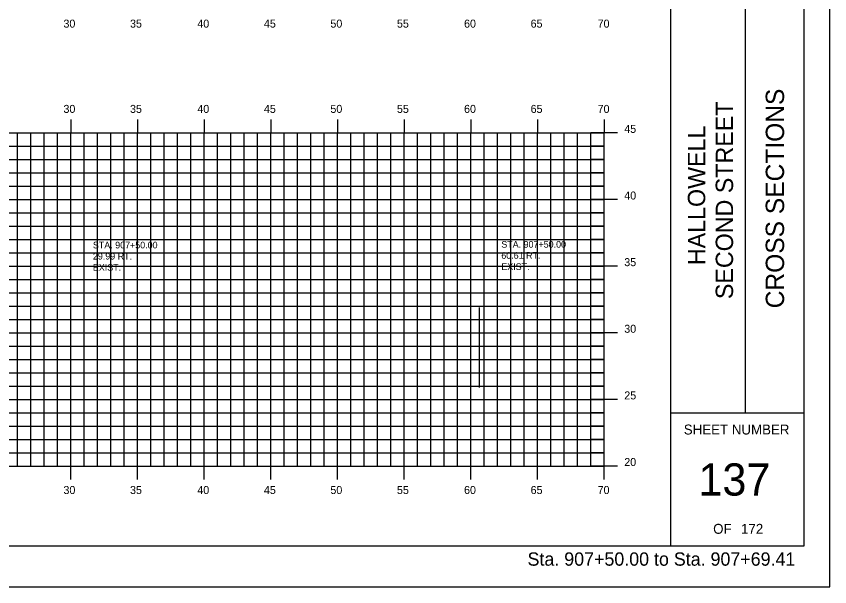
# Model space of a CAD drawing. Extents: x 1025909 to 1026079, y 394697 to 394807.
# Drawn here: x 1026017.6 to 1026078.6, y 394696.5 to 394739.4 of the extents above; entities that cross this region are included whole.
import ezdxf

# ---------------------------------------------------------------- set-up
doc = ezdxf.new("R2010")
doc.units = 0
for name, color, linetype in [('BORDER', 7, 'Continuous'), ('D_Text_Monospaced', 7, 'Continuous'), ('H_V ANNOTATION', 7, 'Continuous'), ('HIGHWAY_TITLE', 7, 'Continuous'), ('MAJOR', 7, 'Continuous'), ('MINOR', 7, 'Continuous'), ('PLOT BOUNDARY', 7, 'Continuous'), ('S_Utilities_UG_Sanitary_Sewer', 7, 'Continuous')]:
    doc.layers.add(name, color=color, linetype=linetype)

msp = doc.modelspace()

# ---------------------------------------------------------------- linework, layer by layer
at = {"layer": 'BORDER'}
for p, q in [((1026066.677, 394699.607), (1026066.677, 394804.61)), ((1026076.677, 394699.607), (1026076.677, 394804.607)), ((1026072.268, 394709.61), (1026072.268, 394744.61)), ((1026066.677, 394709.61), (1026076.677, 394709.61)), ((1025916.677, 394699.607), (1026076.677, 394699.607))]:
    msp.add_line(p, q, dxfattribs=at)
at = {"layer": 'MAJOR'}
for p, q in [((1026021.677, 394731.609), (1026021.677, 394730.607)), ((1026026.677, 394731.609), (1026026.677, 394730.607)), ((1026031.677, 394731.609), (1026031.677, 394730.607)), ((1026036.677, 394731.609), (1026036.677, 394730.607)), ((1026041.677, 394731.609), (1026041.677, 394730.607)), ((1026046.677, 394731.609), (1026046.677, 394730.607)), ((1026051.677, 394731.609), (1026051.677, 394730.607)), ((1026056.677, 394731.609), (1026056.677, 394730.607)), ((1026061.677, 394731.609), (1026061.677, 394730.607)), ((1025921.677, 394730.607), (1026061.677, 394730.607)), ((1026021.677, 394705.607), (1026021.677, 394730.607)), ((1026026.677, 394705.607), (1026026.677, 394730.607)), ((1026031.677, 394705.607), (1026031.677, 394730.607)), ((1026036.677, 394705.607), (1026036.677, 394730.607)), ((1026041.677, 394705.607), (1026041.677, 394730.607)), ((1026046.677, 394705.607), (1026046.677, 394730.607)), ((1026051.677, 394705.607), (1026051.677, 394730.607)), ((1026056.677, 394705.607), (1026056.677, 394730.607)), ((1026062.679, 394730.607), (1026060.675, 394730.607)), ((1026061.677, 394705.607), (1026061.677, 394730.607)), ((1025921.677, 394725.607), (1026061.677, 394725.607)), ((1026062.679, 394725.607), (1026060.675, 394725.607)), ((1025921.677, 394720.607), (1026061.677, 394720.607)), ((1026062.679, 394720.607), (1026060.675, 394720.607)), ((1025921.677, 394715.607), (1026061.677, 394715.607)), ((1026062.679, 394715.607), (1026060.675, 394715.607)), ((1025921.677, 394710.607), (1026061.677, 394710.607)), ((1026062.679, 394710.607), (1026060.675, 394710.607)), ((1025921.677, 394705.607), (1026061.677, 394705.607)), ((1026021.677, 394704.605), (1026021.677, 394705.607)), ((1026026.677, 394704.605), (1026026.677, 394705.607)), ((1026031.677, 394704.605), (1026031.677, 394705.607)), ((1026036.677, 394704.605), (1026036.677, 394705.607)), ((1026041.677, 394704.605), (1026041.677, 394705.607)), ((1026046.677, 394704.605), (1026046.677, 394705.607)), ((1026051.677, 394704.605), (1026051.677, 394705.607)), ((1026056.677, 394704.605), (1026056.677, 394705.607)), ((1026062.679, 394705.607), (1026060.675, 394705.607)), ((1026061.677, 394704.605), (1026061.677, 394705.607))]:
    msp.add_line(p, q, dxfattribs=at)
at = {"layer": 'MINOR'}
for p, q in [((1026017.677, 394705.607), (1026017.677, 394730.607)), ((1026018.677, 394705.607), (1026018.677, 394730.607)), ((1026019.677, 394705.607), (1026019.677, 394730.607)), ((1026020.677, 394705.607), (1026020.677, 394730.607)), ((1026022.677, 394705.607), (1026022.677, 394730.607)), ((1026023.677, 394705.607), (1026023.677, 394730.607)), ((1026024.677, 394705.607), (1026024.677, 394730.607)), ((1026025.677, 394705.607), (1026025.677, 394730.607)), ((1026027.677, 394705.607), (1026027.677, 394730.607)), ((1026028.677, 394705.607), (1026028.677, 394730.607)), ((1026029.677, 394705.607), (1026029.677, 394730.607)), ((1026030.677, 394705.607), (1026030.677, 394730.607)), ((1026032.677, 394705.607), (1026032.677, 394730.607)), ((1026033.677, 394705.607), (1026033.677, 394730.607)), ((1026034.677, 394705.607), (1026034.677, 394730.607)), ((1026035.677, 394705.607), (1026035.677, 394730.607)), ((1026037.677, 394705.607), (1026037.677, 394730.607)), ((1026038.677, 394705.607), (1026038.677, 394730.607)), ((1026039.677, 394705.607), (1026039.677, 394730.607)), ((1026040.677, 394705.607), (1026040.677, 394730.607)), ((1026042.677, 394705.607), (1026042.677, 394730.607)), ((1026043.677, 394705.607), (1026043.677, 394730.607)), ((1026044.677, 394705.607), (1026044.677, 394730.607)), ((1026045.677, 394705.607), (1026045.677, 394730.607)), ((1026047.677, 394705.607), (1026047.677, 394730.607)), ((1026048.677, 394705.607), (1026048.677, 394730.607)), ((1026049.677, 394705.607), (1026049.677, 394730.607)), ((1026050.677, 394705.607), (1026050.677, 394730.607)), ((1026052.677, 394705.607), (1026052.677, 394730.607)), ((1026053.677, 394705.607), (1026053.677, 394730.607)), ((1026054.677, 394705.607), (1026054.677, 394730.607)), ((1026055.677, 394705.607), (1026055.677, 394730.607)), ((1026057.677, 394705.607), (1026057.677, 394730.607)), ((1026058.677, 394705.607), (1026058.677, 394730.607)), ((1026059.677, 394705.607), (1026059.677, 394730.607)), ((1026060.677, 394705.607), (1026060.677, 394730.607)), ((1025921.677, 394729.607), (1026061.677, 394729.607)), ((1026061.677, 394729.607), (1026060.675, 394729.607)), ((1025921.677, 394728.607), (1026061.677, 394728.607)), ((1026061.677, 394728.607), (1026060.675, 394728.607)), ((1025921.677, 394727.607), (1026061.677, 394727.607)), ((1026061.677, 394727.607), (1026060.675, 394727.607)), ((1025921.677, 394726.607), (1026061.677, 394726.607)), ((1026061.677, 394726.607), (1026060.675, 394726.607)), ((1025921.677, 394724.607), (1026061.677, 394724.607)), ((1026061.677, 394724.607), (1026060.675, 394724.607)), ((1025921.677, 394723.607), (1026061.677, 394723.607)), ((1026061.677, 394723.607), (1026060.675, 394723.607)), ((1025921.677, 394722.607), (1026061.677, 394722.607)), ((1026061.677, 394722.607), (1026060.675, 394722.607)), ((1025921.677, 394721.607), (1026061.677, 394721.607)), ((1026061.677, 394721.607), (1026060.675, 394721.607)), ((1025921.677, 394719.607), (1026061.677, 394719.607)), ((1026061.677, 394719.607), (1026060.675, 394719.607)), ((1025921.677, 394718.607), (1026061.677, 394718.607)), ((1026061.677, 394718.607), (1026060.675, 394718.607)), ((1025921.677, 394717.607), (1026061.677, 394717.607)), ((1026061.677, 394717.607), (1026060.675, 394717.607)), ((1025921.677, 394716.607), (1026061.677, 394716.607)), ((1026061.677, 394716.607), (1026060.675, 394716.607)), ((1025921.677, 394714.607), (1026061.677, 394714.607)), ((1026061.677, 394714.607), (1026060.675, 394714.607)), ((1025921.677, 394713.607), (1026061.677, 394713.607)), ((1026061.677, 394713.607), (1026060.675, 394713.607)), ((1025921.677, 394712.607), (1026061.677, 394712.607)), ((1026061.677, 394712.607), (1026060.675, 394712.607)), ((1025921.677, 394711.607), (1026061.677, 394711.607)), ((1026061.677, 394711.607), (1026060.675, 394711.607)), ((1025921.677, 394709.607), (1026061.677, 394709.607)), ((1026061.677, 394709.607), (1026060.675, 394709.607)), ((1025921.677, 394708.607), (1026061.677, 394708.607)), ((1026061.677, 394708.607), (1026060.675, 394708.607)), ((1025921.677, 394707.607), (1026061.677, 394707.607)), ((1026061.677, 394707.607), (1026060.675, 394707.607)), ((1025921.677, 394706.607), (1026061.677, 394706.607)), ((1026061.677, 394706.607), (1026060.675, 394706.607))]:
    msp.add_line(p, q, dxfattribs=at)
at = {"layer": 'PLOT BOUNDARY'}
msp.add_lwpolyline([(1025908.583, 394696.548), (1026078.583, 394696.548), (1026078.583, 394806.548), (1025908.583, 394806.548)], close=True, dxfattribs=at)
at = {"layer": 'S_Utilities_UG_Sanitary_Sewer'}
for p, q in [((1026021.665, 394717.439), (1026021.665, 394711.439)), ((1026052.29, 394717.493), (1026052.29, 394711.493))]:
    msp.add_line(p, q, dxfattribs=at)

# ---------------------------------------------------------------- texts
at = {"layer": 'BORDER'}
for s, height, rotation, p in [('CROSS SECTIONS', 1.37787, 90, (1026075.161, 394717.444)), ('SHEET NUMBER', 0.74527, 360, (1026067.642, 394707.973)), ('137', 2.4194, 360, (1026068.737, 394703.389)), ('OF', 0.7453, 360, (1026069.844, 394700.52)), ('172', 0.7453, 360, (1026071.933, 394700.52))]:
    msp.add_text(s, height=height, rotation=rotation, dxfattribs=at).set_placement(p)
at = {"layer": 'D_Text_Monospaced'}
for s, height, p in [('STA. 907+50.00', 0.49998, (1026053.957, 394721.991)), ('STA. 907+50.00', 0.49998, (1026023.332, 394721.937)), ('29.99 RT.', 0.5, (1026023.332, 394721.103)), ('60.61 RT.', 0.5, (1026053.957, 394721.157)), ('EXIST. ', 0.5, (1026023.332, 394720.263)), ('EXIST. ', 0.5, (1026053.957, 394720.317))]:
    msp.add_text(s, height=height, dxfattribs=at).set_placement(p)
at = {"layer": 'H_V ANNOTATION'}
for s, height, p in [('30', 0.6, (1026021.125, 394738.507)), ('35', 0.6, (1026026.117, 394738.507)), ('40', 0.6, (1026031.163, 394738.507)), ('45', 0.6, (1026036.155, 394738.507)), ('50', 0.6, (1026041.141, 394738.507)), ('55', 0.6, (1026046.133, 394738.507)), ('60', 0.6, (1026051.163, 394738.507)), ('65', 0.6, (1026056.155, 394738.507)), ('70', 0.6, (1026061.179, 394738.507)), ('30', 0.6, (1026021.125, 394732.107)), ('35', 0.6, (1026026.117, 394732.107)), ('40', 0.6, (1026031.163, 394732.107)), ('45', 0.6, (1026036.155, 394732.107)), ('50', 0.6, (1026041.141, 394732.107)), ('55', 0.6, (1026046.133, 394732.107)), ('60', 0.6, (1026051.163, 394732.107)), ('65', 0.6, (1026056.155, 394732.107)), ('70', 0.6, (1026061.179, 394732.107)), ('45', 0.6, (1026063.177, 394730.607)), ('40', 0.6, (1026063.177, 394725.607)), ('35', 0.6, (1026063.177, 394720.607)), ('30', 0.6, (1026063.177, 394715.607)), ('25', 0.6, (1026063.177, 394710.607)), ('20', 0.6, (1026063.177, 394705.607)), ('30', 0.6, (1026021.125, 394703.507)), ('35', 0.6, (1026026.117, 394703.507)), ('40', 0.6, (1026031.163, 394703.507)), ('45', 0.6, (1026036.155, 394703.507)), ('50', 0.6, (1026041.141, 394703.507)), ('55', 0.6, (1026046.133, 394703.507)), ('60', 0.6, (1026051.163, 394703.507)), ('65', 0.6, (1026056.155, 394703.507)), ('70', 0.6, (1026061.179, 394703.507)), ('Sta. 907+50.00 to Sta. 907+69.41', 1.0002, (1026055.925, 394698.126))]:
    msp.add_text(s, height=height, dxfattribs=at).set_placement(p)
at = {"layer": 'HIGHWAY_TITLE'}
for s, height, p in [('SECOND STREET', 1.30428, (1026071.336, 394718.134)), ('HALLOWELL', 1.3043, (1026069.249, 394720.684))]:
    msp.add_text(s, height=height, rotation=90, dxfattribs=at).set_placement(p)

doc.saveas('drawing.dxf')
